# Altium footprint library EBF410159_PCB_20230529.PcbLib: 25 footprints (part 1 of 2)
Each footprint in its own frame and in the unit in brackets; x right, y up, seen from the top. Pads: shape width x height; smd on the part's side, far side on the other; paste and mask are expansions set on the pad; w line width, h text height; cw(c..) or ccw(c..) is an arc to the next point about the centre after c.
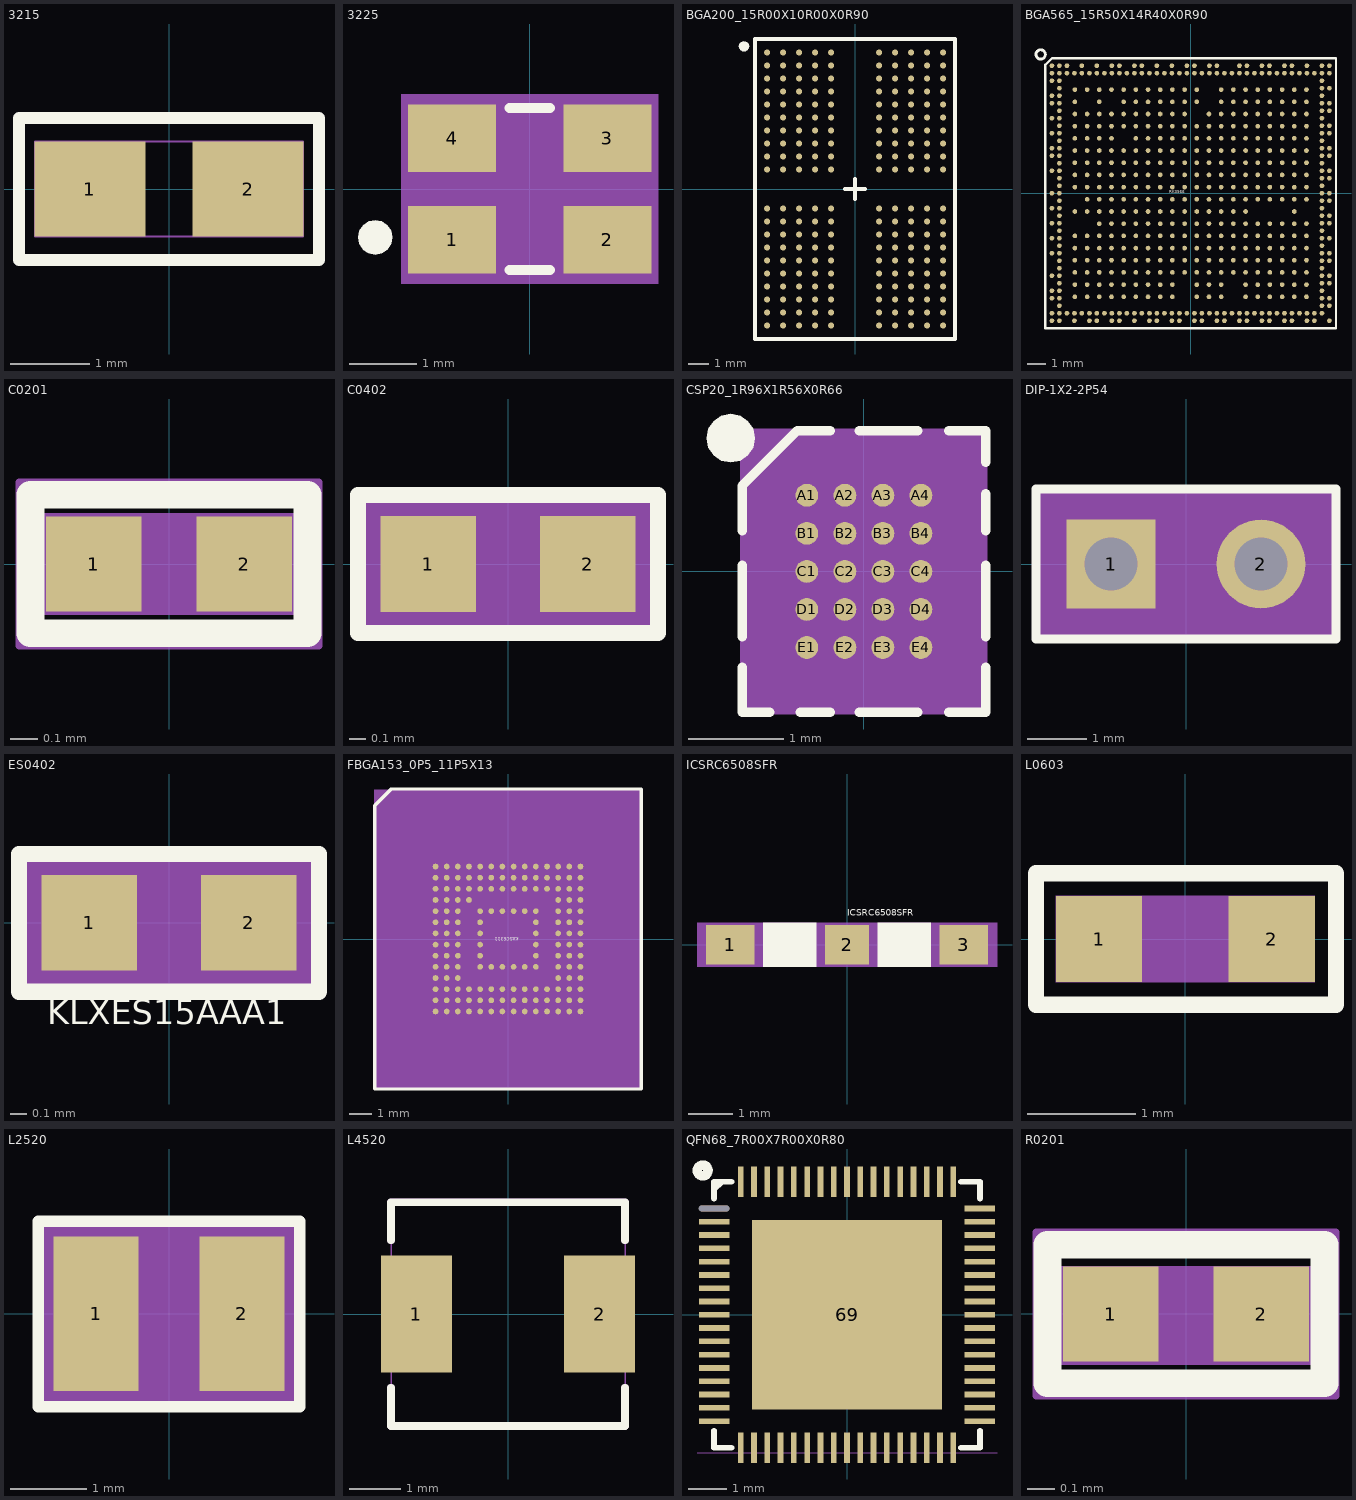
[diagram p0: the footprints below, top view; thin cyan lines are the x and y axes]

## 3215 [mm] "3215"
pads (2):
  rect 1.4x1.2 smd: 1(-1.001,0) 2(1.001,0)
Top Overlay:
  lines w0.15: -1.9,-0.899 1.9,-0.899 1.9,0.899 -1.9,0.899 -1.9,-0.899
Top 3D Body:
  lines w0.025: -1.699,-0.599 -1.699,0.599 1.699,0.599 1.699,-0.599 -1.699,-0.599
Mechanical 14:
  text "2" at 0.848,0 h0.38
  text "1" at -1.153,0 h0.38

## 3225 [mm] "3225"
pads (4):
  rect 1.3x1 smd: 1(-1.15,-0.75) 2(1.15,-0.75) 3(1.15,0.75) 4(-1.15,0.75)
Top Overlay:
  dashed: -2.033,-0.716 -2.052,-0.619 -2.107,-0.536 -2.19,-0.481 -2.288,-0.461 -2.385,-0.481 -2.413,-0.499 -2.468,-0.536 -2.523,-0.619 -2.542,-0.716 -2.523,-0.814 -2.468,-0.896 -2.413,-0.933 -2.385,-0.952 -2.288,-0.971 -2.19,-0.952 -2.107,-0.896 -2.052,-0.814
  lines w0.15: -0.3,-1.2 0.3,-1.2 ; -0.3,1.2 0.3,1.2
Top 3D Body:
  region: -1.9,1.4 -1.9,-1.4 1.9,-1.4 1.9,1.4
Mechanical 14:
  text "2" at 0.784,-0.75 h0.91
  text "4" at -1.516,0.75 h0.91
  text "1" at -1.516,-0.75 h0.91
  text "3" at 0.784,0.75 h0.91
Top Assembly:
  lines w0.15: -1.6,-1.25 1.6,-1.25 1.6,1.25 -1.6,1.25 -1.6,-1.25
3D body: height 3.81, standoff 0, extent -1.9,-1.4 1.9,1.4

## BGA200_15R00X10R00X0R90 [mm] "BGA200_15R00X10R00X0R90"
pads (200):
  round 0.3 smd: A1(-4.4,6.825) A2(-3.6,6.825) A3(-2.8,6.825) A4(-2,6.825) A5(-1.2,6.825) A8(1.2,6.825) A9(2,6.825) A10(2.8,6.825) A11(3.6,6.825) A12(4.4,6.825) AA1(-4.4,-6.175) AA2(-3.6,-6.175) AA3(-2.8,-6.175) AA4(-2,-6.175) AA5(-1.2,-6.175) AA8(1.2,-6.175) AA9(2,-6.175) AA10(2.8,-6.175) AA11(3.6,-6.175) AA12(4.4,-6.175) AB1(-4.4,-6.825) AB2(-3.6,-6.825) AB3(-2.8,-6.825) AB4(-2,-6.825) AB5(-1.2,-6.825) AB8(1.2,-6.825) AB9(2,-6.825) AB10(2.8,-6.825) AB11(3.6,-6.825) AB12(4.4,-6.825) B1(-4.4,6.175) B2(-3.6,6.175) B3(-2.8,6.175) B4(-2,6.175) B5(-1.2,6.175) B8(1.2,6.175) B9(2,6.175) B10(2.8,6.175) B11(3.6,6.175) B12(4.4,6.175) C1(-4.4,5.525) C2(-3.6,5.525) C3(-2.8,5.525) C4(-2,5.525) C5(-1.2,5.525) C8(1.2,5.525) C9(2,5.525) C10(2.8,5.525) C11(3.6,5.525) C12(4.4,5.525) D1(-4.4,4.875) D2(-3.6,4.875) D3(-2.8,4.875) D4(-2,4.875) D5(-1.2,4.875) D8(1.2,4.875) D9(2,4.875) D10(2.8,4.875) D11(3.6,4.875) D12(4.4,4.875) E1(-4.4,4.225) E2(-3.6,4.225) E3(-2.8,4.225) E4(-2,4.225) E5(-1.2,4.225) E8(1.2,4.225) E9(2,4.225) E10(2.8,4.225) E11(3.6,4.225) E12(4.4,4.225) F1(-4.4,3.575) F2(-3.6,3.575) F3(-2.8,3.575) F4(-2,3.575) F5(-1.2,3.575) F8(1.2,3.575) F9(2,3.575) F10(2.8,3.575) F11(3.6,3.575) F12(4.4,3.575) G1(-4.4,2.925) G2(-3.6,2.925) G3(-2.8,2.925) G4(-2,2.925) G5(-1.2,2.925) G8(1.2,2.925) G9(2,2.925) G10(2.8,2.925) G11(3.6,2.925) G12(4.4,2.925) H1(-4.4,2.275) H2(-3.6,2.275) H3(-2.8,2.275) H4(-2,2.275) H5(-1.2,2.275) H8(1.2,2.275) H9(2,2.275) H10(2.8,2.275) H11(3.6,2.275) H12(4.4,2.275) J1(-4.4,1.625) J2(-3.6,1.625) J3(-2.8,1.625) J4(-2,1.625) J5(-1.2,1.625) J8(1.2,1.625) J9(2,1.625) J10(2.8,1.625) J11(3.6,1.625) J12(4.4,1.625) K1(-4.4,0.975) K2(-3.6,0.975) K3(-2.8,0.975) K4(-2,0.975) K5(-1.2,0.975) K8(1.2,0.975) K9(2,0.975) K10(2.8,0.975) K11(3.6,0.975) K12(4.4,0.975) N1(-4.4,-0.975) N2(-3.6,-0.975) N3(-2.8,-0.975) N4(-2,-0.975) N5(-1.2,-0.975) N8(1.2,-0.975) N9(2,-0.975) N10(2.8,-0.975) N11(3.6,-0.975) N12(4.4,-0.975) P1(-4.4,-1.625) P2(-3.6,-1.625) P3(-2.8,-1.625) P4(-2,-1.625) P5(-1.2,-1.625) P8(1.2,-1.625) P9(2,-1.625) P10(2.8,-1.625) P11(3.6,-1.625) P12(4.4,-1.625) R1(-4.4,-2.275) R2(-3.6,-2.275) R3(-2.8,-2.275) R4(-2,-2.275) R5(-1.2,-2.275) R8(1.2,-2.275) R9(2,-2.275) R10(2.8,-2.275) R11(3.6,-2.275) R12(4.4,-2.275) T1(-4.4,-2.925) T2(-3.6,-2.925) T3(-2.8,-2.925) T4(-2,-2.925) T5(-1.2,-2.925) T8(1.2,-2.925) T9(2,-2.925) T10(2.8,-2.925) T11(3.6,-2.925) T12(4.4,-2.925) U1(-4.4,-3.575) U2(-3.6,-3.575) U3(-2.8,-3.575) U4(-2,-3.575) U5(-1.2,-3.575) U8(1.2,-3.575) U9(2,-3.575) U10(2.8,-3.575) U11(3.6,-3.575) U12(4.4,-3.575) V1(-4.4,-4.225) V2(-3.6,-4.225) V3(-2.8,-4.225) V4(-2,-4.225) V5(-1.2,-4.225) V8(1.2,-4.225) V9(2,-4.225) V10(2.8,-4.225) V11(3.6,-4.225) V12(4.4,-4.225) W1(-4.4,-4.875) W2(-3.6,-4.875) W3(-2.8,-4.875) W4(-2,-4.875) W5(-1.2,-4.875) W8(1.2,-4.875) W9(2,-4.875) W10(2.8,-4.875) W11(3.6,-4.875) W12(4.4,-4.875) Y1(-4.4,-5.525) Y2(-3.6,-5.525) Y3(-2.8,-5.525) Y4(-2,-5.525) Y5(-1.2,-5.525) Y8(1.2,-5.525) Y9(2,-5.525) Y10(2.8,-5.525) Y11(3.6,-5.525) Y12(4.4,-5.525)
Top Layer:
  lines w0.254: -4.404,-4.871 -4.4,-4.875
Top Overlay:
  dashed: -5.559,7.385 -5.656,7.366 -5.739,7.311 -5.794,7.228 -5.813,7.131 -5.794,7.033 -5.775,7.005 -5.739,6.95 -5.656,6.895 -5.559,6.876 -5.461,6.895 -5.378,6.95 -5.342,7.005 -5.323,7.033 -5.304,7.131 -5.323,7.228 -5.378,7.311 -5.461,7.366
  lines w0.2: -0.5,0 0,0 ; 0,-0.5 0,0 ; 0,0.5 0,0 ; 0.5,0 0,0 ; -5,-7.5 5,-7.5 5,7.5 -5,7.5 -5,-7.5

## BGA565_15R50X14R40X0R90 [mil] "BGA565_15R50X14R40X0R90"
pads (565):
  round 9.8 smd: 1A1(-243.1,217.5) 1A2(-217.5,217.5) 1A3(-191.9,217.5) 1A4(-166.3,217.5) 1A5(-140.7,217.51) 1A6(-115.19,217.5) 1A7(-89.6,217.5) 1A8(-64,217.5) 1A9(-38.4,217.5) 1A10(-12.81,217.5) 1A11(12.81,217.5) 1A13(64,217.5) 1A14(89.6,217.5) 1A15(115.19,217.5) 1A16(140.7,217.51) 1A17(166.3,217.5) 1A18(191.9,217.5) 1A19(217.5,217.5) 1A20(243.1,217.5) 1B1(-243.1,191.9) 1B3(-191.9,191.9) 1B5(-140.7,191.89) 1B6(-115.19,191.9) 1B7(-89.6,191.9) 1B8(-64,191.9) 1B9(-38.4,191.9) 1B10(-12.8,191.89) 1B11(12.8,191.89) 1B13(64,191.9) 1B14(89.6,191.9) 1B15(115.19,191.9) 1B16(140.7,191.89) 1B17(166.3,191.9) 1B18(191.9,191.9) 1B19(217.5,191.9) 1B20(243.1,191.9) 1C1(-243.1,166.3) 1C2(-217.5,166.3) 1C3(-191.9,166.3) 1C4(-166.3,166.3) 1C5(-140.7,166.3) 1C6(-115.2,166.3) 1C7(-89.6,166.3) 1C8(-64,166.3) 1C9(-38.4,166.3) 1C10(-12.8,166.3) 1C12(38.4,166.3) 1C13(64,166.3) 1C14(89.6,166.3) 1C15(115.2,166.3) 1C16(140.7,166.3) 1C17(166.3,166.3) 1C18(191.9,166.3) 1C19(217.5,166.3) 1C20(243.1,166.3) 1D1(-243.1,140.7) 1D2(-217.51,140.7) 1D3(-191.89,140.7) 1D4(-166.3,140.7) 1D5(-140.7,140.7) 1D6(-115.2,140.7) 1D7(-89.6,140.7) 1D8(-63.99,140.7) 1D9(-38.4,140.7) 1D10(-12.8,140.7) 1D11(12.8,140.7) 1D12(38.4,140.7) 1D13(63.99,140.7) 1D14(89.6,140.7) 1D15(115.2,140.7) 1D16(140.7,140.7) 1D17(166.3,140.7) 1D18(191.89,140.7) 1D19(217.51,140.7) 1D20(243.1,140.7) 1E1(-243.1,115.2) 1E2(-217.5,115.19) 1E3(-191.9,115.19) 1E4(-166.3,115.2) 1E6(-115.2,115.2) 1E7(-89.6,115.2) 1E8(-64,115.19) 1E9(-38.4,115.2) 1E10(-12.8,115.2) 1E11(12.8,115.2) 1E12(38.4,115.2) 1E13(64,115.19) 1E14(89.6,115.2) 1E15(115.2,115.2) 1E16(140.7,115.2) 1E17(166.3,115.2) 1E18(191.9,115.19) 1E19(217.5,115.19) 1E20(243.1,115.2) 1F1(-243.1,89.6) 1F2(-217.5,89.6) 1F3(-191.9,89.6) 1F4(-166.3,89.6) 1F5(-140.7,89.6) 1F6(-115.2,89.6) 1F7(-89.6,89.6) 1F8(-64,89.6) 1F9(-38.4,89.6) 1F10(-12.8,89.6) 1F11(12.8,89.6) 1F12(38.4,89.6) 1F13(64,89.6) 1F14(89.6,89.6) 1F15(115.2,89.6) 1F16(140.7,89.6) 1F17(166.3,89.6) 1F18(191.9,89.6) 1F19(217.5,89.6) 1F20(243.1,89.6) 1G1(-243.1,64) 1G2(-217.5,64) 1G3(-191.9,64) 1G4(-166.3,64) 1G5(-140.7,63.99) 1G6(-115.19,64) 1G7(-89.6,64) 1G8(-64,64) 1G9(-38.4,64) 1G10(-12.81,64) 1G11(12.81,64) 1G12(38.4,64) 1G13(64,64) 1G14(89.6,64) 1G15(115.19,64) 1G16(140.7,63.99) 1G17(166.3,64) 1G18(191.9,64) 1G19(217.5,64) 1G20(243.1,64) 1H1(-243.1,38.4) 1H2(-217.5,38.4) 1H3(-191.9,38.4) 1H4(-166.3,38.4) 1H5(-140.7,38.4) 1H6(-115.2,38.4) 1H7(-89.6,38.4) 1H8(-64,38.4) 1H9(-38.4,38.4) 1H10(-12.8,38.4) 1H11(12.8,38.4) 1H12(38.4,38.4) 1H13(64,38.4) 1H14(89.6,38.4) 1H15(115.2,38.4) 1H16(140.7,38.4) 1H17(166.3,38.4) 1H18(191.9,38.4) 1H19(217.5,38.4) 1H20(243.1,38.4) 1J1(-243.1,12.8) 1J2(-217.5,12.81) 1J3(-191.89,12.8) 1J4(-166.3,12.8) 1J5(-140.7,12.8) 1J6(-115.2,12.8) 1J7(-89.6,12.8) 1J8(-64,12.81) 1J9(-38.4,12.8) 1J10(-12.8,12.8) 1J11(12.8,12.8) 1J12(38.4,12.8) 1J13(64,12.81) 1J14(89.6,12.8) 1J15(115.2,12.8) 1J16(140.7,12.8) 1J17(166.3,12.8) 1J18(191.89,12.8) 1J19(217.5,12.81) 1J20(243.1,12.8) 1K2(-217.5,-12.81) 1K3(-191.89,-12.8) 1K4(-166.3,-12.8) 1K5(-140.7,-12.8) 1K6(-115.2,-12.8) 1K7(-89.6,-12.8) 1K8(-64,-12.81) 1K9(-38.4,-12.8) 1K10(-12.8,-12.8) 1K11(12.8,-12.8) 1K12(38.4,-12.8) 1K13(64,-12.81) 1K14(89.6,-12.8) 1K15(115.2,-12.8) 1K16(140.7,-12.8) 1K17(166.3,-12.8) 1K18(191.89,-12.8) 1K19(217.5,-12.81) 1K20(243.1,-12.8) 1L1(-243.1,-38.4) 1L2(-217.5,-38.4) 1L3(-191.9,-38.4) 1L4(-166.3,-38.4) 1L5(-140.7,-38.4) 1L6(-115.2,-38.4) 1L7(-89.6,-38.4) 1L8(-64,-38.4) 1L9(-38.4,-38.4) 1L10(-12.8,-38.4) 1L11(12.8,-38.4) 1L12(38.4,-38.4) 1L13(64,-38.4) 1L14(89.6,-38.4) 1L15(115.2,-38.4) 1L19(217.5,-38.4) 1M3(-191.9,-64) 1M4(-166.3,-64) 1M5(-140.7,-63.99) 1M6(-115.19,-64) 1M7(-89.6,-64) 1M8(-64,-64) 1M9(-38.4,-64) 1M10(-12.81,-64) 1M11(12.81,-64) 1M12(38.4,-64) 1M13(64,-64) 1M14(89.6,-64) 1M15(115.19,-64) 1M16(140.7,-63.99) 1M17(166.3,-64) 1M18(191.9,-64) 1M19(217.5,-64) 1M20(243.1,-64) 1N1(-243.1,-89.6) 1N2(-217.5,-89.6) 1N3(-191.9,-89.6) 1N4(-166.3,-89.6) 1N5(-140.7,-89.6) 1N6(-115.2,-89.6) 1N7(-89.6,-89.6) 1N8(-64,-89.6) 1N9(-38.4,-89.6) 1N10(-12.8,-89.6) 1N11(12.8,-89.6) 1N12(38.4,-89.6) 1N13(64,-89.6) 1N14(89.6,-89.6) 1N15(115.2,-89.6) 1N16(140.7,-89.6) 1N17(166.3,-89.6) 1N18(191.9,-89.6) 1N19(217.5,-89.6) 1N20(243.1,-89.6) 1P1(-243.1,-115.2) 1P2(-217.5,-115.19) 1P3(-191.9,-115.19) 1P4(-166.3,-115.2) 1P5(-140.7,-115.2) 1P6(-115.2,-115.2) 1P7(-89.6,-115.2) 1P8(-64,-115.19) 1P9(-38.4,-115.2) 1P10(-12.8,-115.2) 1P11(12.8,-115.2) 1P12(38.4,-115.2) 1P13(64,-115.19) 1P14(89.6,-115.2) 1P15(115.2,-115.2) 1P16(140.7,-115.2) 1P17(166.3,-115.2) 1P18(191.9,-115.19) 1P19(217.5,-115.19) 1P20(243.1,-115.2) 1R1(-243.1,-140.7) 1R2(-217.51,-140.7) 1R3(-191.89,-140.7) 1R4(-166.3,-140.7) 1R5(-140.7,-140.7) 1R6(-115.2,-140.7) 1R7(-89.6,-140.7) 1R8(-63.99,-140.7) 1R9(-38.4,-140.7) 1R10(-12.8,-140.7) 1R11(12.8,-140.7) 1R12(38.4,-140.7) 1R13(63.99,-140.7) 1R14(89.6,-140.7) 1R15(115.2,-140.7) 1R16(140.7,-140.7) 1R17(166.3,-140.7) 1R18(191.89,-140.7) 1R19(217.51,-140.7) 1R20(243.1,-140.7) 1T1(-243.1,-166.3) 1T2(-217.5,-166.3) 1T3(-191.9,-166.3) 1T4(-166.3,-166.3) 1T5(-140.7,-166.3) 1T6(-115.2,-166.3) 1T7(-89.6,-166.3) 1T8(-64,-166.3) 1T9(-38.4,-166.3) 1T10(-12.8,-166.3) 1T11(12.8,-166.3) 1T12(38.4,-166.3) 1T13(64,-166.3) 1T14(89.6,-166.3) 1T15(115.2,-166.3) 1T16(140.7,-166.3) 1T17(166.3,-166.3) 1T18(191.9,-166.3) 1T19(217.5,-166.3) 1T20(243.1,-166.3) 1U1(-243.1,-191.9) 1U2(-217.5,-191.9) 1U3(-191.9,-191.9) 1U4(-166.3,-191.9) 1U5(-140.7,-191.89) 1U6(-115.19,-191.9) 1U7(-89.6,-191.9) 1U8(-64,-191.9) 1U9(-38.4,-191.9) 1U11(12.8,-191.89) 1U12(38.4,-191.9) 1U13(64,-191.9) 1U15(115.19,-191.9) 1U16(140.7,-191.89) 1U17(166.3,-191.9) 1U18(191.9,-191.9) 1U19(217.5,-191.9) 1U20(243.1,-191.9) 1V1(-243.1,-217.5) 1V2(-217.5,-217.5) 1V3(-191.9,-217.5) 1V4(-166.3,-217.5) 1V5(-140.7,-217.51) 1V6(-115.19,-217.5) 1V7(-89.6,-217.5) 1V8(-64,-217.5) 1V9(-38.4,-217.5) 1V11(12.81,-217.5) 1V12(38.4,-217.5) 1V13(64,-217.5) 1V15(115.19,-217.5) 1V16(140.7,-217.51) 1V17(166.3,-217.5) 1V18(191.9,-217.5) 1V19(217.5,-217.5) 1V20(243.1,-217.5) A1(-291.3,267.7) A2(-275.6,267.7) A3(-259.8,267.7) A5(-228.4,267.7) A7(-196.9,267.7) A9(-165.4,267.7) A10(-149.6,267.7) A12(-118.1,267.7) A13(-102.4,267.7) A15(-70.9,267.7) A17(-39.4,267.7) A19(-7.9,267.7) A20(7.9,267.7) A22(39.4,267.7) A23(55.1,267.7) A26(102.4,267.7) A27(118.1,267.7) A29(149.6,267.7) A30(165.4,267.7) A32(196.9,267.7) A33(212.6,267.7) A35(244.1,267.7) A37(275.6,267.7) A38(291.3,267.7) AA2(-275.59,-47.2) AA37(275.59,-47.2) AA38(291.3,-47.21) AB1(-291.3,-63) AB2(-275.6,-63) AB37(275.6,-63) AB38(291.3,-63) AC2(-275.6,-78.7) AC37(275.6,-78.7) AD1(-291.3,-94.5) AD2(-275.6,-94.5) AD37(275.6,-94.5) AD38(291.3,-94.5) AE2(-275.6,-110.2) AE37(275.6,-110.2) AF1(-291.3,-126.01) AF2(-275.59,-126) AF37(275.59,-126) AF38(291.3,-126.01) AG2(-275.6,-141.7) AG37(275.6,-141.7) AG38(291.3,-141.7) AH2(-275.6,-157.5) AH37(275.6,-157.5) AJ1(-291.3,-173.2) AJ2(-275.6,-173.2) AJ37(275.6,-173.2) AJ38(291.3,-173.2) AK2(-275.6,-189) AK37(275.6,-189) AK38(291.3,-189) AL1(-291.3,-204.69) AL2(-275.59,-204.7) AL37(275.59,-204.7) AM1(-291.3,-220.5) AM2(-275.6,-220.5) AM37(275.6,-220.5) AM38(291.3,-220.5) AN2(-275.6,-236.2) AN37(275.6,-236.2) AN38(291.3,-236.2) AP1(-291.3,-252) AP2(-275.6,-252) AP3(-259.81,-252) AP4(-244.1,-252.01) AP5(-228.4,-252) AP6(-212.6,-252) AP7(-196.9,-252) AP8(-181.1,-252) AP9(-165.4,-252.01) AP10(-149.6,-252) AP11(-133.9,-252) AP12(-118.1,-252) AP13(-102.4,-252) AP14(-86.6,-252.01) AP15(-70.89,-252) AP16(-55.1,-252) AP17(-39.4,-252) AP18(-23.6,-252) AP19(-7.91,-252) AP20(7.91,-252) AP21(23.6,-252) AP22(39.4,-252) AP23(55.1,-252) AP24(70.89,-252) AP25(86.6,-252.01) AP26(102.4,-252) AP27(118.1,-252) AP28(133.9,-252) AP29(149.6,-252) AP30(165.4,-252.01) AP31(181.1,-252) AP32(196.9,-252) AP33(212.6,-252) AP34(228.4,-252) AP35(244.1,-252.01) AP36(259.81,-252) AP37(275.6,-252) AR1(-291.3,-267.7) AR2(-275.6,-267.7) AR4(-244.1,-267.7) AR6(-212.6,-267.7) AR7(-196.9,-267.7) AR9(-165.4,-267.7) AR10(-149.6,-267.7) AR12(-118.1,-267.7) AR14(-86.6,-267.7) AR15(-70.9,-267.7) AR17(-39.4,-267.7) AR18(-23.6,-267.7) AR20(7.9,-267.7) AR21(23.6,-267.7) AR23(55.1,-267.7) AR24(70.9,-267.7) AR26(102.4,-267.7) AR27(118.1,-267.7) AR29(149.6,-267.7) AR30(165.4,-267.7) AR32(196.9,-267.7) AR33(212.6,-267.7) AR35(244.1,-267.7) AR36(259.8,-267.7) AR38(291.3,-267.7) B1(-291.3,252) B2(-275.6,252) B3(-259.81,252) B4(-244.1,252.01) B5(-228.4,252) B6(-212.6,252) B7(-196.9,252) B8(-181.1,252) B9(-165.4,252.01) B10(-149.6,252) B11(-133.9,252) B12(-118.1,252) B13(-102.4,252) B14(-86.6,252.01) B15(-70.89,252) B16(-55.1,252) B17(-39.4,252) B18(-23.6,252) B19(-7.91,252) B20(7.91,252) B21(23.6,252) B22(39.4,252) B23(55.1,252) B24(70.89,252) B25(86.6,252.01) B26(102.4,252) B27(118.1,252) B28(133.9,252) B29(149.6,252) B30(165.4,252.01) B31(181.1,252) B32(196.9,252) B33(212.6,252) B34(228.4,252) B35(244.1,252.01) B36(259.81,252) B37(275.6,252) B38(291.3,252) C1(-291.3,236.2) C2(-275.6,236.2) C37(275.6,236.2) D2(-275.6,220.5) D37(275.6,220.5) D38(291.3,220.5) E1(-291.3,204.69) E2(-275.59,204.7) E37(275.59,204.7) F1(-291.3,189) F2(-275.6,189) F37(275.6,189) F38(291.3,189) G2(-275.6,173.2) G37(275.6,173.2) G38(291.3,173.2) H1(-291.3,157.5) H2(-275.6,157.5) H37(275.6,157.5) J2(-275.6,141.7) J37(275.6,141.7) J38(291.3,141.7) K1(-291.3,126.01) K2(-275.59,126) K37(275.59,126) K38(291.3,126.01) L2(-275.6,110.2) L37(275.6,110.2) M1(-291.3,94.5) M2(-275.6,94.5) M37(275.6,94.5) M38(291.3,94.5) N1(-291.3,78.7) N2(-275.6,78.7) N37(275.6,78.7) N38(291.3,78.7) P2(-275.6,63) P37(275.6,63) R1(-291.3,47.21) R2(-275.59,47.2) R37(275.59,47.2) R38(291.3,47.21) T2(-275.59,31.5) T37(275.59,31.5) T38(291.3,31.49) U2(-275.6,15.7) U37(275.6,15.7) V1(-291.3,0) V2(-275.6,0) V37(275.6,0) V38(291.3,0) W2(-275.6,-15.7) W37(275.6,-15.7) W38(291.3,-15.7) Y1(-291.3,-31.49) Y2(-275.59,-31.5) Y37(275.59,-31.5)
Top Overlay:
  circle w5.91: c-314.96,291.34 r9.84
  lines w5: -305.1,-283.5 -305.1,269.7 -291.3,283.49 305.1,283.5 305.1,-283.5 -305.1,-283.5
  text "RK3566" at -45,0 h6

## C0201 [mm] "C0201"
pads (2):
  rect 0.35x0.35 smd: 1(-0.275,0) 2(0.275,0)
Top Overlay:
  lines w0.102: -0.508,-0.254 -0.508,0.254 0.508,0.254 0.508,-0.254 -0.508,-0.254
Top 3D Body:
  region: -0.475,-0.175 -0.475,0.175 0.475,0.175 0.475,-0.175
Top Assembly:
  lines w0.025: -0.55,-0.3 0.55,-0.3 0.55,0.3 -0.55,0.3 -0.55,-0.3 ; -0.475,-0.175 0.475,-0.175 0.475,0.175 -0.475,0.175 -0.475,-0.175
3D body: height 3.81, standoff 0, extent -0.475,-0.175 0.475,0.175

## C0402 [mm] "C0402"
pads (2):
  rect 0.599x0.599 smd: 1(-0.5,0) 2(0.5,0)
Top Overlay:
  lines w0.102: -0.94,-0.432 -0.94,0.432 0.94,0.432 0.94,-0.432 -0.94,-0.432
Top 3D Body:
  region: 0.94,0.432 0.94,-0.432 -0.94,-0.432 -0.94,0.432
Top Assembly:
  dashed: -0.94,-0.432 -0.94,0.432 0.94,0.432 0.94,-0.432
3D body: height 3.81, standoff 0, extent -0.94,-0.432 0.94,0.432

## CSP20_1R96X1R56X0R66 [mil] "CSP20_1R96X1R56X0R66"
pads (20):
  round 9.45 smd: A1(-23.62,31.5) A2(-7.87,31.5) A3(7.87,31.5) A4(23.62,31.5) B1(-23.62,15.75) B2(-7.87,15.75) B3(7.87,15.75) B4(23.62,15.75) C1(-23.62,0) C2(-7.87,0) C3(7.87,0) C4(23.62,0) D1(-23.62,-15.75) D2(-7.87,-15.75) D3(7.87,-15.75) D4(23.62,-15.75) E1(-23.62,-31.5) E2(-7.87,-31.5) E3(7.87,-31.5) E4(23.62,-31.5)
Top Overlay:
  dashed: -55.12,65.15 -58.96,64.39 -62.21,62.21 -64.39,58.96 -65.15,55.12 -64.39,51.28 -63.66,50.19 -62.21,48.03 -58.96,45.85 -55.12,45.09 -51.28,45.85 -48.03,48.03 -46.58,50.19 -45.85,51.28 -45.09,55.12 -45.85,58.96 -48.03,62.21 -51.28,64.39
  lines w3.94: -50.39,-39.73 -50.39,-58.27 -38.92,-58.27 ; -50.39,-26.98 -50.39,2.45 ; -50.39,16.92 -50.39,35.43 -27.56,58.27 -13.91,58.27 ; -26.42,-58.27 -13.91,-58.27 ; -1.89,-58.27 22.39,-58.27 ; -1.89,58.27 22.39,58.27 ; 35.14,-58.27 50.39,-58.27 50.39,-39.73 ; 35.14,58.27 50.39,58.27 50.39,45.13 ; 50.39,-26.98 50.39,2.45 ; 50.39,16.92 50.39,32.13
Top 3D Body:
  region: -51.18,59.06 -51.18,-59.06 51.18,-59.06 51.18,59.06
  region: -30.16,39.37 -30.16,-39.37 31.5,-39.37 31.5,39.37
Mechanical 14:
  text "D1" at -23.62,-23.75 h10
  text "D2" at -7.87,-23.75 h10
  text "E1" at -23.62,-39.5 h10
  text "E2" at -7.87,-39.5 h10
  text "A4" at 23.62,23.5 h10
  text "A1" at -23.62,23.5 h10
  text "D3" at 7.87,-23.75 h10
  text "D4" at 23.62,-23.75 h10
  text "E3" at 7.87,-39.5 h10
  text "E4" at 23.62,-39.5 h10
  text "B1" at -23.62,7.75 h10
  text "A3" at 7.87,23.5 h10
  text "A2" at -7.87,23.5 h10
  text "B2" at -7.87,7.75 h10
  text "B3" at 7.87,7.75 h10
  text "B4" at 23.62,7.75 h10
  text "C1" at -23.62,-8 h10
  text "C2" at -7.87,-8 h10
  text "C3" at 7.87,-8 h10
  text "C4" at 23.62,-8 h10
3D body: height 150, standoff 0, extent -51.18,-59.06 51.18,59.06
3D body: height 150, standoff 0, extent -30.16,-39.37 31.5,39.37

## DIP-1X2-2P54 [mm] "DIP-1X2-2P54"
pads (2):
  rect 1.5x1.5 hole 0.9: 1(-1.27,0)
  round 1.5 hole 0.9: 2(1.27,0)
Top Overlay:
  lines w0.15: -2.54,-1.27 -2.54,1.27 2.54,1.27 2.54,-1.27 -2.54,-1.27
Top 3D Body:
  region: -2.54,-1.27 2.54,-1.27 2.54,1.27 -2.54,1.27
Mechanical 14:
  text "2" at 1.27,0.254 h0.64
  text "1" at -1.27,0.254 h0.64
Top Assembly:
  lines w0.025: -2.54,-1.27 -2.54,1.27 2.54,1.27 2.54,-1.27 -2.54,-1.27
3D body: height 3.81, standoff 0, extent -2.54,-1.27 2.54,1.27

## ES0402 [mm] "ES0402"
pads (2):
  rect 0.599x0.599 smd: 1(-0.5,0) 2(0.5,0)
Top Overlay:
  lines w0.102: -0.94,-0.432 -0.94,0.432 0.94,0.432 0.94,-0.432 -0.94,-0.432
  text "KLXES15AAA1" at -0.762,-0.635 h0.15
Top 3D Body:
  region: 0.94,0.432 0.94,-0.432 -0.94,-0.432 -0.94,0.432
Mechanical 14:
  text "1" at -0.5,-0.254 h0.64
  text "2" at 0.5,-0.254 h0.64
Top Assembly:
  dashed: -0.94,-0.432 -0.94,0.432 0.94,0.432 0.94,-0.432
3D body: height 3.81, standoff 0, extent -0.94,-0.432 0.94,0.432

## FBGA153_0P5_11P5X13 [mil] "FBGA153_0P5_11P5X13"
pads (153):
  round 10 smd: A1(-127.95,127.95) A2(-108.27,127.95) A3(-88.58,127.95) A4(-68.9,127.95) A5(-49.21,127.95) A6(-29.53,127.95) A7(-9.84,127.95) A8(9.84,127.95) A9(29.53,127.95) A10(49.21,127.95) A11(68.9,127.95) A12(88.58,127.95) A13(108.27,127.95) A14(127.95,127.95) B1(-127.95,108.27) B2(-108.27,108.27) B3(-88.58,108.27) B4(-68.9,108.27) B5(-49.21,108.27) B6(-29.53,108.27) B7(-9.84,108.27) B8(9.84,108.27) B9(29.53,108.27) B10(49.21,108.27) B11(68.9,108.27) B12(88.58,108.27) B13(108.27,108.27) B14(127.95,108.27) C1(-127.95,88.58) C2(-108.27,88.58) C3(-88.58,88.58) C4(-68.9,88.58) C5(-49.21,88.58) C6(-29.53,88.58) C7(-9.84,88.58) C8(9.84,88.58) C9(29.53,88.58) C10(49.21,88.58) C11(68.9,88.58) C12(88.58,88.58) C13(108.27,88.58) C14(127.95,88.58) D1(-127.95,68.9) D2(-108.27,68.9) D3(-88.58,68.9) D4(-68.9,68.9) D12(88.58,68.9) D13(108.27,68.9) D14(127.95,68.9) E1(-127.95,49.21) E2(-108.27,49.21) E3(-88.58,49.21) E5(-49.21,49.21) E6(-29.53,49.21) E7(-9.84,49.21) E8(9.84,49.21) E9(29.53,49.21) E10(49.21,49.21) E12(88.58,49.21) E13(108.27,49.21) E14(127.95,49.21) F1(-127.95,29.53) F2(-108.27,29.53) F3(-88.58,29.53) F5(-49.21,29.53) F10(49.21,29.53) F12(88.58,29.53) F13(108.27,29.53) F14(127.95,29.53) G1(-127.95,9.84) G2(-108.27,9.84) G3(-88.58,9.84) G5(-49.21,9.84) G10(49.21,9.84) G12(88.58,9.84) G13(108.27,9.84) G14(127.95,9.84) H1(-127.95,-9.84) H2(-108.27,-9.84) H3(-88.58,-9.84) H5(-49.21,-9.84) H10(49.21,-9.84) H12(88.58,-9.84) H13(108.27,-9.84) H14(127.95,-9.84) J1(-127.95,-29.53) J2(-108.27,-29.53) J3(-88.58,-29.53) J5(-49.21,-29.53) J10(49.21,-29.53) J12(88.58,-29.53) J13(108.27,-29.53) J14(127.95,-29.53) K1(-127.95,-49.21) K2(-108.27,-49.21) K3(-88.58,-49.21) K5(-49.21,-49.21) K6(-29.53,-49.21) K7(-9.84,-49.21) K8(9.84,-49.21) K9(29.53,-49.21) K10(49.21,-49.21) K12(88.58,-49.21) K13(108.27,-49.21) K14(127.95,-49.21) L1(-127.95,-68.9) L2(-108.27,-68.9) L3(-88.58,-68.9) L12(88.58,-68.9) L13(108.27,-68.9) L14(127.95,-68.9) M1(-127.95,-88.58) M2(-108.27,-88.58) M3(-88.58,-88.58) M4(-68.9,-88.58) M5(-49.21,-88.58) M6(-29.53,-88.58) M7(-9.84,-88.58) M8(9.84,-88.58) M9(29.53,-88.58) M10(49.21,-88.58) M11(68.9,-88.58) M12(88.58,-88.58) M13(108.27,-88.58) M14(127.95,-88.58) N1(-127.95,-108.27) N2(-108.27,-108.27) N3(-88.58,-108.27) N4(-68.9,-108.27) N5(-49.21,-108.27) N6(-29.53,-108.27) N7(-9.84,-108.27) N8(9.84,-108.27) N9(29.53,-108.27) N10(49.21,-108.27) N11(68.9,-108.27) N12(88.58,-108.27) N13(108.27,-108.27) N14(127.95,-108.27) P1(-127.95,-127.95) P2(-108.27,-127.95) P3(-88.58,-127.95) P4(-68.9,-127.95) P5(-49.21,-127.95) P6(-29.53,-127.95) P7(-9.84,-127.95) P8(9.84,-127.95) P9(29.53,-127.95) P10(49.21,-127.95) P11(68.9,-127.95) P12(88.58,-127.95) P13(108.27,-127.95) P14(127.95,-127.95)
Top Overlay:
  lines w6: -235.35,-264.87 -235.35,235.77 -206.24,264.87 235.35,264.87 235.35,-264.87 -235.35,-264.87
  text "KASC6311" at 19.2,3 h6
Top 3D Body:
  region: -236.22,-263.78 236.22,-263.78 236.22,263.78 -236.22,263.78
Top Component Center:
  lines w1: -10,0 10,0 ; 0,-10 0,10
Mechanical 14:
  text "A1" at -119.95,127.95 h10
  text "A10" at 61.21,127.95 h10
  text "A11" at 80.9,127.95 h10
  text "A12" at 100.58,127.95 h10
  text "A13" at 120.27,127.95 h10
  text "A14" at 139.95,127.95 h10
  text "A2" at -100.27,127.95 h10
  text "A8" at 17.84,127.95 h10
  text "A9" at 37.53,127.95 h10
  text "B1" at -119.95,108.27 h10
  text "B10" at 61.21,108.27 h10
  text "B11" at 80.9,108.27 h10
  text "B12" at 100.58,108.27 h10
  text "B13" at 120.27,108.27 h10
  text "B14" at 139.95,108.27 h10
  text "B7" at -1.84,108.27 h10
  text "B8" at 17.84,108.27 h10
  text "B9" at 37.53,108.27 h10
  text "C1" at -119.95,88.58 h10
  text "C10" at 61.21,88.58 h10
  text "C11" at 80.9,88.58 h10
  text "C12" at 100.58,88.58 h10
  text "C13" at 120.27,88.58 h10
  text "C14" at 139.95,88.58 h10
  text "C3" at -80.58,88.58 h10
  text "C7" at -1.84,88.58 h10
  text "C8" at 17.84,88.58 h10
  text "C9" at 37.53,88.58 h10
  text "D1" at -119.95,68.9 h10
  text "D12" at 100.58,68.9 h10
  text "D13" at 120.27,68.9 h10
  text "D14" at 139.95,68.9 h10
  text "D2" at -100.27,68.9 h10
  text "D3" at -80.58,68.9 h10
  text "D4" at -60.9,68.9 h10
  text "E1" at -119.95,49.21 h10
  text "E12" at 100.58,49.21 h10
  text "E13" at 120.27,49.21 h10
  text "E14" at 139.95,49.21 h10
  text "E2" at -100.27,49.21 h10
  text "E3" at -80.58,49.21 h10
  text "F1" at -119.95,29.53 h10
  text "F12" at 100.58,29.53 h10
  text "F13" at 120.27,29.53 h10
  text "F14" at 139.95,29.53 h10
  text "F2" at -100.27,29.53 h10
  text "F3" at -80.58,29.53 h10
  text "G1" at -119.95,9.84 h10
  text "G12" at 100.58,9.84 h10
  text "G13" at 120.27,9.84 h10
  text "G14" at 139.95,9.84 h10
  text "G2" at -100.27,9.84 h10
  text "H1" at -119.95,-9.84 h10
  text "H12" at 100.58,-9.84 h10
  text "H13" at 120.27,-9.84 h10
  text "H14" at 139.95,-9.84 h10
  text "H2" at -100.27,-9.84 h10
  text "H3" at -80.58,-9.84 h10
  text "J1" at -119.95,-29.53 h10
  text "J12" at 100.58,-29.53 h10
  text "J13" at 120.27,-29.53 h10
  text "J14" at 139.95,-29.53 h10
  text "J2" at -100.27,-29.53 h10
  text "J3" at -80.58,-29.53 h10
  text "K1" at -119.95,-49.21 h10
  text "K12" at 100.58,-49.21 h10
  text "K13" at 120.27,-49.21 h10
  text "K14" at 139.95,-49.21 h10
  text "K2" at -100.27,-49.21 h10
  text "K3" at -80.58,-49.21 h10
  text "L1" at -119.95,-68.9 h10
  text "L12" at 100.58,-68.9 h10
  text "L13" at 120.27,-68.9 h10
  text "L14" at 139.95,-68.9 h10
  text "L2" at -100.27,-68.9 h10
  text "L3" at -80.58,-68.9 h10
  text "M1" at -119.95,-88.58 h10
  text "M10" at 61.21,-88.58 h10
  text "M11" at 80.9,-88.58 h10
  text "M12" at 100.58,-88.58 h10
  text "M13" at 120.27,-88.58 h10
  text "M14" at 139.95,-88.58 h10
  text "M2" at -100.27,-88.58 h10
  text "M3" at -80.58,-88.58 h10
  text "M7" at -1.84,-88.58 h10
  text "M8" at 17.84,-88.58 h10
  text "M9" at 37.53,-88.58 h10
  text "N1" at -119.95,-108.27 h10
  text "N10" at 61.21,-108.27 h10
  text "N11" at 80.9,-108.27 h10
  text "N12" at 100.58,-108.27 h10
  text "N13" at 120.27,-108.27 h10
  text "N14" at 139.95,-108.27 h10
  text "N3" at -80.58,-108.27 h10
  text "N6" at -21.53,-108.27 h10
  text "N7" at -1.84,-108.27 h10
  text "N8" at 17.84,-108.27 h10
  text "N9" at 37.53,-108.27 h10
  text "P1" at -119.95,-127.95 h10
  text "P11" at 80.9,-127.95 h10
  text "P12" at 100.58,-127.95 h10
  text "P13" at 120.27,-127.95 h10
  text "P14" at 139.95,-127.95 h10
  text "P2" at -100.27,-127.95 h10
  text "P8" at 17.84,-127.95 h10
  text "P9" at 37.53,-127.95 h10
  text "G3" at -80.58,9.84 h10
  text "K10" at 61.21,-49.21 h10
  text "K6" at -21.53,-49.21 h10
  text "K7" at -1.84,-49.21 h10
  text "P10" at 61.21,-127.95 h10
  text "P7" at -1.84,-127.95 h10
  text "A7" at -1.84,127.95 h10
  text "C5" at -41.21,88.58 h10
  text "E10" at 61.21,49.21 h10
  text "E5" at -41.21,49.21 h10
  text "E8" at 17.84,49.21 h10
  text "E9" at 37.53,49.21 h10
  text "F10" at 61.21,29.53 h10
  text "G10" at 61.21,9.84 h10
  text "C6" at -21.53,88.58 h10
  text "M4" at -60.9,-88.58 h10
  text "N4" at -60.9,-108.27 h10
  text "P3" at -80.58,-127.95 h10
  text "P5" at -41.21,-127.95 h10
  text "B4" at -60.9,108.27 h10
  text "B2" at -100.27,108.27 h10
  text "M6" at -21.53,-88.58 h10
  text "A5" at -41.21,127.95 h10
  text "B5" at -41.21,108.27 h10
  text "C2" at -100.27,88.58 h10
  text "A4" at -60.9,127.95 h10
  text "B6" at -21.53,108.27 h10
  text "M5" at -41.21,-88.58 h10
  text "A3" at -80.58,127.95 h10
  text "B3" at -80.58,108.27 h10
  text "E6" at -21.53,49.21 h10
  text "F5" at -41.21,29.53 h10
  text "J10" at 61.21,-29.53 h10
  text "K9" at 37.53,-49.21 h10
  text "K5" at -41.21,-49.21 h10
  text "A6" at -21.53,127.95 h10
  text "C4" at -60.9,88.58 h10
  text "E7" at -1.84,49.21 h10
  text "G5" at -41.21,9.84 h10
  text "H10" at 61.21,-9.84 h10
  text "J5" at -41.21,-29.53 h10
  text "K8" at 17.84,-49.21 h10
  text "N2" at -100.27,-108.27 h10
  text "N5" at -41.21,-108.27 h10
  text "P4" at -60.9,-127.95 h10
  text "P6" at -21.53,-127.95 h10
  text "H5" at -41.21,-9.84 h10
Top Assembly:
  circle w6: c-188.98,220.47 r26.4
  lines w6: -228.35,-257.87 -228.35,232.87 -203.35,257.87 228.35,257.87 228.35,-257.87 -228.35,-257.87
3D body: height 150, standoff 0, extent -236.22,-263.78 236.22,263.78

## ICSRC6508SFR [mm] "ICSRC6508SFR"
pads (3):
  rect 1.1x0.9 smd: 1(-2.65,0) 3(2.65,0)
  rect 1x0.9 smd: 2(0,0)
Top Overlay:
  dashed: 0.7,0.5 0.7,-0.5 1.9,-0.5 1.9,0.5
  dashed: -1.9,0.5 -1.9,-0.5 -0.7,-0.5 -0.7,0.5
  text "ICSRC6508SFR" at 0,0.655 h0.15
Top 3D Body:
  region: 3.4,-0.5 3.4,0.5 -3.4,0.5 -3.4,-0.5
Top Assembly:
  lines w0.1: -3.35,-0.45 -3.35,0.45 3.35,0.45 3.35,-0.45 -3.35,-0.45
3D body: height 3.81, standoff 0, extent -3.4,-0.5 3.4,0.5

## L0603 [mil] "L0603"
pads (2):
  rect 31.5x31.5 smd: 1(-31.5,0) 2(31.5,0)
Top Overlay:
  lines w6: -54.5,-24 -54.5,24 55,24 55,-24 -54.5,-24
Top 3D Body:
  region: -47.24,-15.75 47.24,-15.75 47.24,15.75 -47.24,15.75
3D body: height 150, standoff 0, extent -47.24,-15.75 47.24,15.75

## L2520 [mil] "L2520"
pads (2):
  rect 44x80 smd: 1(-37.75,0) 2(37.75,0)
Top Overlay:
  lines w6: -67.68,-48.15 -67.67,-48.15 67.67,-48.15 67.67,47.92 -67.68,47.92 -67.68,-48.15
Top 3D Body:
  region: -65,-45 65,-45 65,45 -65,45
Mechanical 14:
  text "1" at -33.03,0 h11.81
  text "2" at 42.47,0 h11.81
3D body: height 150, standoff 0, extent -65,-45 65,45

## L4520 [mm] "L4520"
pads (2):
  rect 1.4x2.3 smd: 1(-1.803,-0.003) 2(1.798,-0.003)
Top Overlay:
  lines w0.15: -2.303,-1.453 -2.303,-2.202 2.297,-2.202 2.297,-1.453 ; -2.303,1.448 -2.303,2.197 2.297,2.197 2.297,1.448
Top 3D Body:
  lines w0.025: -2.303,-2.202 2.303,-2.202 2.303,2.202 -2.303,2.202 -2.303,-2.202
Mechanical 14:
  text "2" at 1.544,-0.003 h0.64
  text "1" at -2.057,-0.003 h0.64
Top Assembly:
  lines w0.15: -2.303,-1.453 -2.303,-2.202 2.297,-2.202 2.297,-1.453 ; -2.303,1.448 -2.303,2.197 2.297,2.197 2.297,1.448

## QFN68_7R00X7R00X0R80 [mil] "QFN68_7R00X7R00X0R80"
pads (69):
  oval 31.5x5.9 smd: 1(-137.8,110.24)
  rect 31.5x5.9 smd: 2(-137.8,96.46) 3(-137.8,82.68) 4(-137.8,68.9) 5(-137.8,55.12) 6(-137.8,41.34) 7(-137.8,27.56) 8(-137.8,13.78) 9(-137.8,0) 10(-137.8,-13.78) 11(-137.8,-27.56) 12(-137.8,-41.34) 13(-137.8,-55.12) 14(-137.8,-68.9) 15(-137.8,-82.68) 16(-137.8,-96.46) 17(-137.8,-110.24) 35(137.8,-110.24) 36(137.8,-96.46) 37(137.8,-82.68) 38(137.8,-68.9) 39(137.8,-55.12) 40(137.8,-41.34) 41(137.8,-27.56) 42(137.8,-13.78) 43(137.8,0) 44(137.8,13.78) 45(137.8,27.56) 46(137.8,41.34) 47(137.8,55.12) 48(137.8,68.9) 49(137.8,82.68) 50(137.8,96.46) 51(137.8,110.24)
  rect 5.9x31.5 smd: 18(-110.24,-137.8) 19(-96.46,-137.8) 20(-82.68,-137.8) 21(-68.9,-137.8) 22(-55.12,-137.8) 23(-41.34,-137.8) 24(-27.56,-137.8) 25(-13.78,-137.8) 26(0,-137.8) 27(13.78,-137.8) 28(27.56,-137.8) 29(41.34,-137.8) 30(55.12,-137.8) 31(68.9,-137.8) 32(82.68,-137.8) 33(96.46,-137.8) 34(110.24,-137.8) 52(110.24,137.8) 53(96.46,137.8) 54(82.68,137.8) 55(68.9,137.8) 56(55.12,137.8) 57(41.34,137.8) 58(27.56,137.8) 59(13.78,137.8) 60(0,137.8) 61(-13.78,137.8) 62(-27.56,137.8) 63(-41.34,137.8) 64(-55.12,137.8) 65(-68.9,137.8) 66(-82.68,137.8) 67(-96.46,137.8) 68(-110.24,137.8)
  rect 196.85x196.85 smd: 69(0,0)
Top Overlay:
  circle w9.84: c-149.61,149.61 r5.57
  lines w5.91: -137.8,-120.08 -137.8,-137.8 -119.69,-137.8 ; -137.8,120.47 -137.8,137.8 -119.69,137.8 ; -137.8,129.92 -129.92,137.8 ; 118.11,-137.8 137.8,-137.8 137.8,-120.08 ; 118.11,137.8 137.8,137.8 137.8,120.47
  text "RK809-5" at 0,13.8 h6
Mechanical 14:
  text "7" at -137.8,37.56 h25
  text "3" at -137.8,92.68 h25
  text "8" at -137.8,23.78 h25
  text "6" at -137.8,51.34 h25
  text "5" at -137.8,65.12 h25
  text "4" at -137.8,78.9 h25
  text "9" at -137.8,10 h25
  text "69" at 0,20 h25
Top Assembly:
  lines w1: -155.51,-142.91 155.51,-142.91

## R0201 [mm] "R0201"
pads (2):
  rect 0.35x0.35 smd: 1(-0.275,0) 2(0.275,0)
Top Overlay:
  lines w0.102: -0.508,-0.254 -0.508,0.254 0.508,0.254 0.508,-0.254 -0.508,-0.254
Top 3D Body:
  region: -0.475,-0.175 -0.475,0.175 0.475,0.175 0.475,-0.175
Top Assembly:
  lines w0.025: -0.475,0.175 -0.475,-0.175 0.475,-0.175 0.475,0.175 ; -0.55,-0.3 0.55,-0.3 0.55,0.3 -0.55,0.3 -0.55,-0.3
3D body: height 3.81, standoff 0, extent -0.475,-0.175 0.475,0.175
